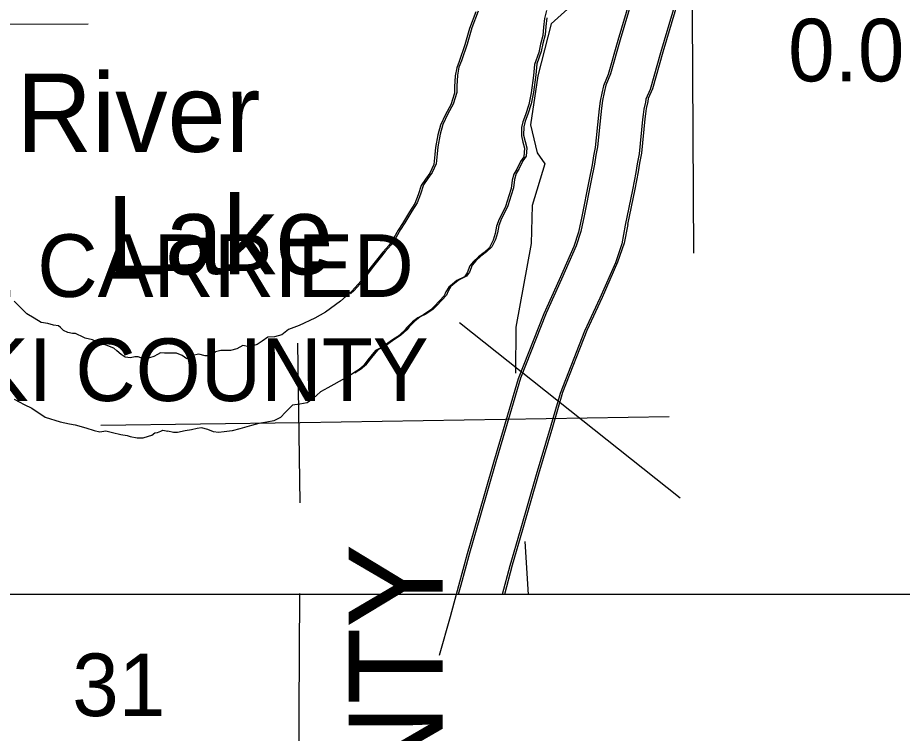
# Model space of a CAD drawing. Extents: x 1127717 to 1741049, y 2026793 to 2244711.
# Drawn here: x 1243987 to 1246972, y 2123128 to 2125542 of the extents above; entities that cross this region are included whole.
import ezdxf

# ---------------------------------------------------------------- set-up
doc = ezdxf.new("R2010")
doc.units = 0
for name, color, linetype in [('1', 7, 'Continuous'), ('10', 7, 'Continuous'), ('2', 7, 'Continuous'), ('25', 7, 'Continuous'), ('30', 7, 'Continuous'), ('5', 7, 'Continuous'), ('9', 7, 'Continuous')]:
    doc.layers.add(name, color=color, linetype=linetype)

msp = doc.modelspace()

# ---------------------------------------------------------------- linework, layer by layer
at = {"layer": '1'}
msp.add_lwpolyline([(1238438.2, 2155644.2), (1269451.6, 2155644.2), (1269451.6, 2123596.1), (1238438.2, 2123596.1)], close=True, dxfattribs=at)
at = {"layer": '10'}
for points in [[(1246080.6, 2125697.5), (1246012.5, 2125465.1), (1245979.7, 2125350.8), (1245963.1, 2125312.1), (1245958.1, 2125287.6), (1245952.5, 2125260.5), (1245948.5, 2125234.5), (1245946.4, 2125213.5), (1245935.5, 2125104.6), (1245929.8, 2125075.9), (1245925.1, 2125045.8), (1245914.6, 2124990.2), (1245890.3, 2124872)], [(1246088.5, 2125699.8), (1246020.3, 2125467.4), (1245987.5, 2125353.1), (1245971, 2125314.4), (1245966, 2125289.9), (1245960.3, 2125262.8), (1245956.4, 2125236.8), (1245954.2, 2125215.8), (1245943.4, 2125106.9), (1245937.7, 2125078.2), (1245933, 2125048.1), (1245922.5, 2124992.5), (1245898.1, 2124874.2)], [(1246224.7, 2125655.6), (1246156.5, 2125423.3), (1246121.3, 2125300.4), (1246107, 2125267), (1246105, 2125257.3), (1246100.1, 2125233.9), (1246097.4, 2125215.7), (1246095.6, 2125198.5), (1246084, 2125082.5), (1246077.5, 2125049.7), (1246073, 2125020.4), (1246061.8, 2124961.2), (1246037.2, 2124841.7)], [(1246232.5, 2125657.9), (1246164.4, 2125425.6), (1246129.1, 2125302.6), (1246114.9, 2125269.3), (1246112.9, 2125259.5), (1246108, 2125236.2), (1246105.2, 2125218), (1246103.5, 2125200.8), (1246091.9, 2125084.8), (1246085.4, 2125052), (1246080.8, 2125022.7), (1246069.7, 2124963.5), (1246045, 2124844)], [(1245890.1, 2124871.2), (1245879.7, 2124818.1), (1245863.6, 2124769.9), (1245814.1, 2124657.8), (1245761.8, 2124543.2), (1245675.7, 2124323.5), (1245639.3, 2124200.6), (1245592.9, 2124041.8), (1245538.4, 2123853.9), (1245503.2, 2123733.5), (1245474.2, 2123624.8), (1245445.9, 2123520.8), (1245408.9, 2123389.9)], [(1245897.9, 2124873.5), (1245887.6, 2124820.4), (1245871.4, 2124772.2), (1245821.9, 2124660.1), (1245769.6, 2124545.5), (1245683.6, 2124325.8), (1245647.1, 2124202.9), (1245600.7, 2124044.1), (1245546.3, 2123856.2), (1245511.1, 2123735.7), (1245482.1, 2123627.1), (1245473.6, 2123596.1)], [(1246037.3, 2124842.4), (1246025.1, 2124779.7), (1246003.6, 2124715.6), (1245950.9, 2124596.4), (1245899.9, 2124484.7), (1245817.7, 2124274.8), (1245783.2, 2124158.3), (1245736.9, 2123999.9), (1245682.5, 2123812), (1245647.7, 2123693.1), (1245621.8, 2123596.1)], [(1246045.2, 2124844.7), (1246032.9, 2124782), (1246011.4, 2124717.9), (1245958.8, 2124598.7), (1245907.8, 2124486.9), (1245825.6, 2124277.1), (1245791, 2124160.6), (1245744.8, 2124002.2), (1245690.3, 2123814.3), (1245655.6, 2123695.4), (1245629.1, 2123596.1)]]:
    msp.add_lwpolyline(points, dxfattribs=at)
at = {"layer": '2'}
for points in [[(1246239.7, 2126294.9), (1246236.2, 2126289.7), (1246227.1, 2126273.5), (1246213.6, 2126250.2), (1246191.9, 2126219.3), (1246167.2, 2126182.2), (1246157.1, 2126165.5), (1246139.9, 2126142), (1246130, 2126132.4), (1246114.2, 2126110.4), (1246104.5, 2126096.5), (1246098.1, 2126089.5), (1246083.2, 2126074.6), (1245952.7, 2125825.4), (1245876.4, 2125602.7), (1245787.4, 2125521.7), (1245741.7, 2125346.1), (1245716.8, 2125181.3), (1245740, 2125086.5), (1245765.3, 2125049), (1245723.4, 2124908.3), (1245719.7, 2124780.5), (1245668.2, 2124498.3), (1245667.1, 2124343.4)], [(1245697.7, 2123775.4), (1245709.4, 2123596.1)]]:
    msp.add_lwpolyline(points, dxfattribs=at)
at = {"layer": '30'}
msp.add_line((1245478, 2124514.3), (1246222, 2123921.9), dxfattribs=at)
at = {"layer": '5'}
for points in [[(1246262.8, 2125569.3), (1246262.7, 2125554), (1246267.9, 2124748.2)], [(1243783.1, 2125520.3), (1244224.9, 2125521.5)], [(1244940, 2123905.7), (1244932.5, 2124443.8)], [(1244267.6, 2124167.9), (1244939.8, 2124176.5), (1246185.5, 2124197.1)], [(1244995.3, 2120648.1), (1244986.5, 2121489.7), (1244934.6, 2122801.7), (1244938.4, 2123599.9)]]:
    msp.add_lwpolyline(points, dxfattribs=at)
at = {"layer": '9'}
for points in [[(1245532.5, 2125561.9), (1245511.6, 2125506.2), (1245495.8, 2125450.7), (1245476.9, 2125395), (1245468.1, 2125372.8), (1245463.4, 2125345.6), (1245460.9, 2125309.4), (1245460.6, 2125287.4), (1245448.7, 2125248.5), (1245430.7, 2125215.9), (1245413.8, 2125179.4), (1245404.7, 2125147.1), (1245396.5, 2125104.3), (1245394.2, 2125080.7), (1245390.7, 2125046.5), (1245377.5, 2125018.1), (1245362.6, 2124997.6), (1245348.3, 2124976.2), (1245338.7, 2124944.3), (1245327.1, 2124915), (1245308.4, 2124886.9), (1245285.1, 2124847.6), (1245270.3, 2124825.7), (1245256, 2124799.7), (1245239.3, 2124773.2), (1245218.5, 2124751), (1245201.6, 2124730), (1245179.5, 2124701.3), (1245158.3, 2124673.7), (1245144.4, 2124653.8), (1245114.5, 2124619.8), (1245076, 2124585.7), (1245025.2, 2124549.1), (1244989.8, 2124528.6), (1244936.1, 2124504), (1244901.1, 2124490.4), (1244877.6, 2124472.7), (1244853.4, 2124465.5), (1244830.5, 2124463.9), (1244811.4, 2124451.3), (1244795.2, 2124439.8), (1244768, 2124431.5), (1244746.9, 2124435.9), (1244726.3, 2124424.8), (1244705, 2124419.1), (1244672.5, 2124419.2), (1244653.7, 2124414.7), (1244641.6, 2124401.8), (1244619.1, 2124401.6), (1244597.5, 2124407), (1244576.2, 2124402.4), (1244557, 2124390.8), (1244541.2, 2124402.4), (1244523, 2124410.4), (1244512.5, 2124410.6)], [(1245540.3, 2125564.2), (1245519.5, 2125508.5), (1245503.6, 2125453), (1245484.8, 2125397.3), (1245475.9, 2125375), (1245471.2, 2125347.9), (1245468.8, 2125311.7), (1245468.4, 2125289.7), (1245456.6, 2125250.8), (1245438.5, 2125218.2), (1245421.6, 2125181.7), (1245412.6, 2125149.4), (1245404.3, 2125106.5), (1245402, 2125082.9), (1245398.5, 2125048.8), (1245385.4, 2125020.4), (1245370.5, 2124999.9), (1245356.1, 2124978.5), (1245346.6, 2124946.6), (1245334.9, 2124917.2), (1245316.3, 2124889.2), (1245292.9, 2124849.9), (1245278.1, 2124828), (1245263.9, 2124802), (1245247.2, 2124775.5), (1245226.4, 2124753.3), (1245209.5, 2124732.3), (1245187.4, 2124703.6), (1245166.2, 2124676), (1245152.3, 2124656), (1245122.3, 2124622.1), (1245109.9, 2124611.1)], [(1245771, 2125566.3), (1245764.2, 2125540.1), (1245761.6, 2125510.5), (1245758.4, 2125482.3), (1245750.8, 2125453.1), (1245745.6, 2125425.4), (1245730.8, 2125384.4), (1245726.9, 2125347.7), (1245719.6, 2125288.9), (1245711.2, 2125249.6), (1245700.3, 2125214.7), (1245691.5, 2125190.4), (1245687, 2125172.3), (1245686.4, 2125143.2), (1245691.5, 2125122.3), (1245696.6, 2125101.5), (1245694.9, 2125072.9), (1245683.9, 2125057.5), (1245670.6, 2125031.1), (1245660.6, 2125014.3), (1245655.2, 2124994.1), (1245651.6, 2124965.9), (1245644.3, 2124941.2), (1245632.9, 2124904.8)], [(1245772.1, 2125542.4), (1245769.5, 2125512.8), (1245766.3, 2125484.6), (1245758.6, 2125455.4), (1245753.5, 2125427.7), (1245738.7, 2125386.7), (1245734.7, 2125350), (1245727.4, 2125291.2), (1245719.1, 2125251.9), (1245708.1, 2125217), (1245699.3, 2125192.7), (1245694.9, 2125174.6), (1245694.2, 2125145.5), (1245699.3, 2125124.6), (1245704.4, 2125103.7), (1245702.7, 2125075.1), (1245691.7, 2125059.8), (1245678.5, 2125033.4), (1245668.5, 2125016.6), (1245663.1, 2124996.4), (1245659.4, 2124968.2), (1245652.1, 2124943.5), (1245640.7, 2124907.1)], [(1245632.9, 2124904.8), (1245622.5, 2124884), (1245611.1, 2124862.6), (1245602.3, 2124838.8), (1245597.6, 2124813.6), (1245591.2, 2124791.4), (1245579, 2124766.5), (1245560.5, 2124750.5), (1245541.4, 2124735.9), (1245524.9, 2124719.9), (1245512.4, 2124704.5), (1245503.1, 2124681.2), (1245494, 2124667.9), (1245468.4, 2124655.6), (1245454.2, 2124643.7), (1245441.1, 2124632.8), (1245431.5, 2124617), (1245425.4, 2124604.3), (1245409.9, 2124586.8), (1245392.5, 2124567.3), (1245381.4, 2124556.5), (1245355.9, 2124539.7), (1245337.2, 2124530.1), (1245319.1, 2124516.1), (1245300.2, 2124497), (1245292, 2124486.8), (1245270.1, 2124467.1), (1245252, 2124455.6), (1245235.4, 2124443.6), (1245218.7, 2124432.1), (1245194.6, 2124419.8), (1245182.6, 2124405.5), (1245168.6, 2124387.5), (1245152.7, 2124367), (1245138.6, 2124355.1), (1245121, 2124343.6), (1245102.4, 2124330), (1245092, 2124325.7)], [(1245640.7, 2124907.1), (1245630.3, 2124886.3), (1245619, 2124864.9), (1245610.2, 2124841.1), (1245605.4, 2124815.9), (1245599.1, 2124793.7), (1245586.8, 2124768.8), (1245568.3, 2124752.7), (1245549.3, 2124738.2), (1245532.7, 2124722.2), (1245520.2, 2124706.8), (1245510.9, 2124683.5), (1245501.8, 2124670.2), (1245476.2, 2124657.9), (1245462.1, 2124646), (1245448.9, 2124635.1), (1245439.4, 2124619.3), (1245433.3, 2124606.6), (1245417.8, 2124589.1), (1245400.4, 2124569.6), (1245389.2, 2124558.8), (1245363.7, 2124542), (1245345.1, 2124532.4), (1245327, 2124518.4), (1245308.1, 2124499.3), (1245299.9, 2124489.1), (1245278, 2124469.4), (1245259.9, 2124457.8), (1245243.2, 2124445.8), (1245226.6, 2124434.3), (1245202.5, 2124422.1), (1245190.4, 2124407.8), (1245176.5, 2124389.8), (1245160.6, 2124369.3), (1245146.4, 2124357.4), (1245128.8, 2124345.9), (1245124.8, 2124343)], [(1244481.6, 2124410.3), (1244469.1, 2124412), (1244458.7, 2124405.7), (1244445.9, 2124398.9), (1244432, 2124395.1), (1244419.1, 2124394.8), (1244402.1, 2124394.9), (1244393.5, 2124398.2), (1244381.6, 2124397.9), (1244367.2, 2124394.6), (1244349.6, 2124397.1), (1244336.4, 2124406.3), (1244321.7, 2124418), (1244311, 2124427.3), (1244284.8, 2124437.2), (1244262.7, 2124444.1), (1244239.5, 2124455.1), (1244214.4, 2124461.5), (1244202.8, 2124466.3), (1244188.1, 2124472.9), (1244182.1, 2124476.3), (1244172.1, 2124476.5), (1244156, 2124479.7), (1244141.4, 2124487.3), (1244131.2, 2124497.1), (1244124, 2124502.4), (1244107.5, 2124505.1), (1244088.4, 2124510.1), (1244065.4, 2124513.6), (1244042.6, 2124528.1), (1244017.3, 2124542.5), (1243993.2, 2124567.9), (1243974.3, 2124585.5)], [(1244512.5, 2124410.6), (1244499.1, 2124410.2), (1244481.6, 2124410.3)], [(1245092, 2124325.7), (1245033.1, 2124293.5), (1245009, 2124279.7), (1244983.7, 2124257), (1244963.7, 2124242.4), (1244938.8, 2124238.1), (1244913.9, 2124235.4), (1244890.2, 2124211.2), (1244873.2, 2124193.7), (1244851.6, 2124181.5), (1244827.8, 2124177.3), (1244800.9, 2124172.5), (1244775.2, 2124165.8), (1244736.6, 2124155.1), (1244710.8, 2124147.9), (1244682.9, 2124145.1), (1244664, 2124143), (1244648, 2124145.1), (1244627.8, 2124152.5), (1244606.7, 2124158.9), (1244592.3, 2124156), (1244573.4, 2124151.4), (1244552, 2124148.8), (1244526.3, 2124143), (1244512.3, 2124143.1), (1244493.4, 2124147.2)], [(1243974.7, 2124255.6), (1244008.1, 2124237.3), (1244034.9, 2124225), (1244079, 2124194), (1244129.8, 2124178.1), (1244161.4, 2124171.9), (1244180.4, 2124168.8), (1244217.1, 2124158.2), (1244245.3, 2124149.3), (1244263.8, 2124145.3), (1244284.2, 2124147.8), (1244306.3, 2124142.3), (1244334.9, 2124135.9), (1244356, 2124132.4), (1244366.6, 2124128.7), (1244389.6, 2124124.2), (1244409.6, 2124125.2), (1244427.9, 2124130.1), (1244439.3, 2124133.4), (1244449.1, 2124141.6), (1244458, 2124142.9), (1244469.4, 2124147.6), (1244476.8, 2124150.8), (1244493.4, 2124147.2)]]:
    msp.add_lwpolyline(points, dxfattribs=at)

# ---------------------------------------------------------------- texts
at = {"layer": '25'}
msp.add_text('0.0', height=211.2, dxfattribs=at).set_placement((1246586.6, 2125327.5))
at = {"layer": '30'}
for s, p in [('MILEAGE CARRIED', (1242718.5, 2124600.1)), ('IN PULASKI COUNTY', (1242548.6, 2124248.8))]:
    msp.add_text(s, height=211.2, dxfattribs=at).set_placement(p)
msp.add_text('COUNTY', height=316.8, rotation=90, dxfattribs=at).set_placement((1245420.9, 2121977.8))
at = {"layer": '5'}
msp.add_text('31', height=211.2, dxfattribs=at).set_placement((1244170.6, 2123185.7))
at = {"layer": '9'}
for s, p in [('River', (1243982.4, 2125089.6)), ('Lake', (1244287.2, 2124676.3))]:
    msp.add_text(s, height=264, dxfattribs=at).set_placement(p)

doc.saveas('drawing.dxf')
